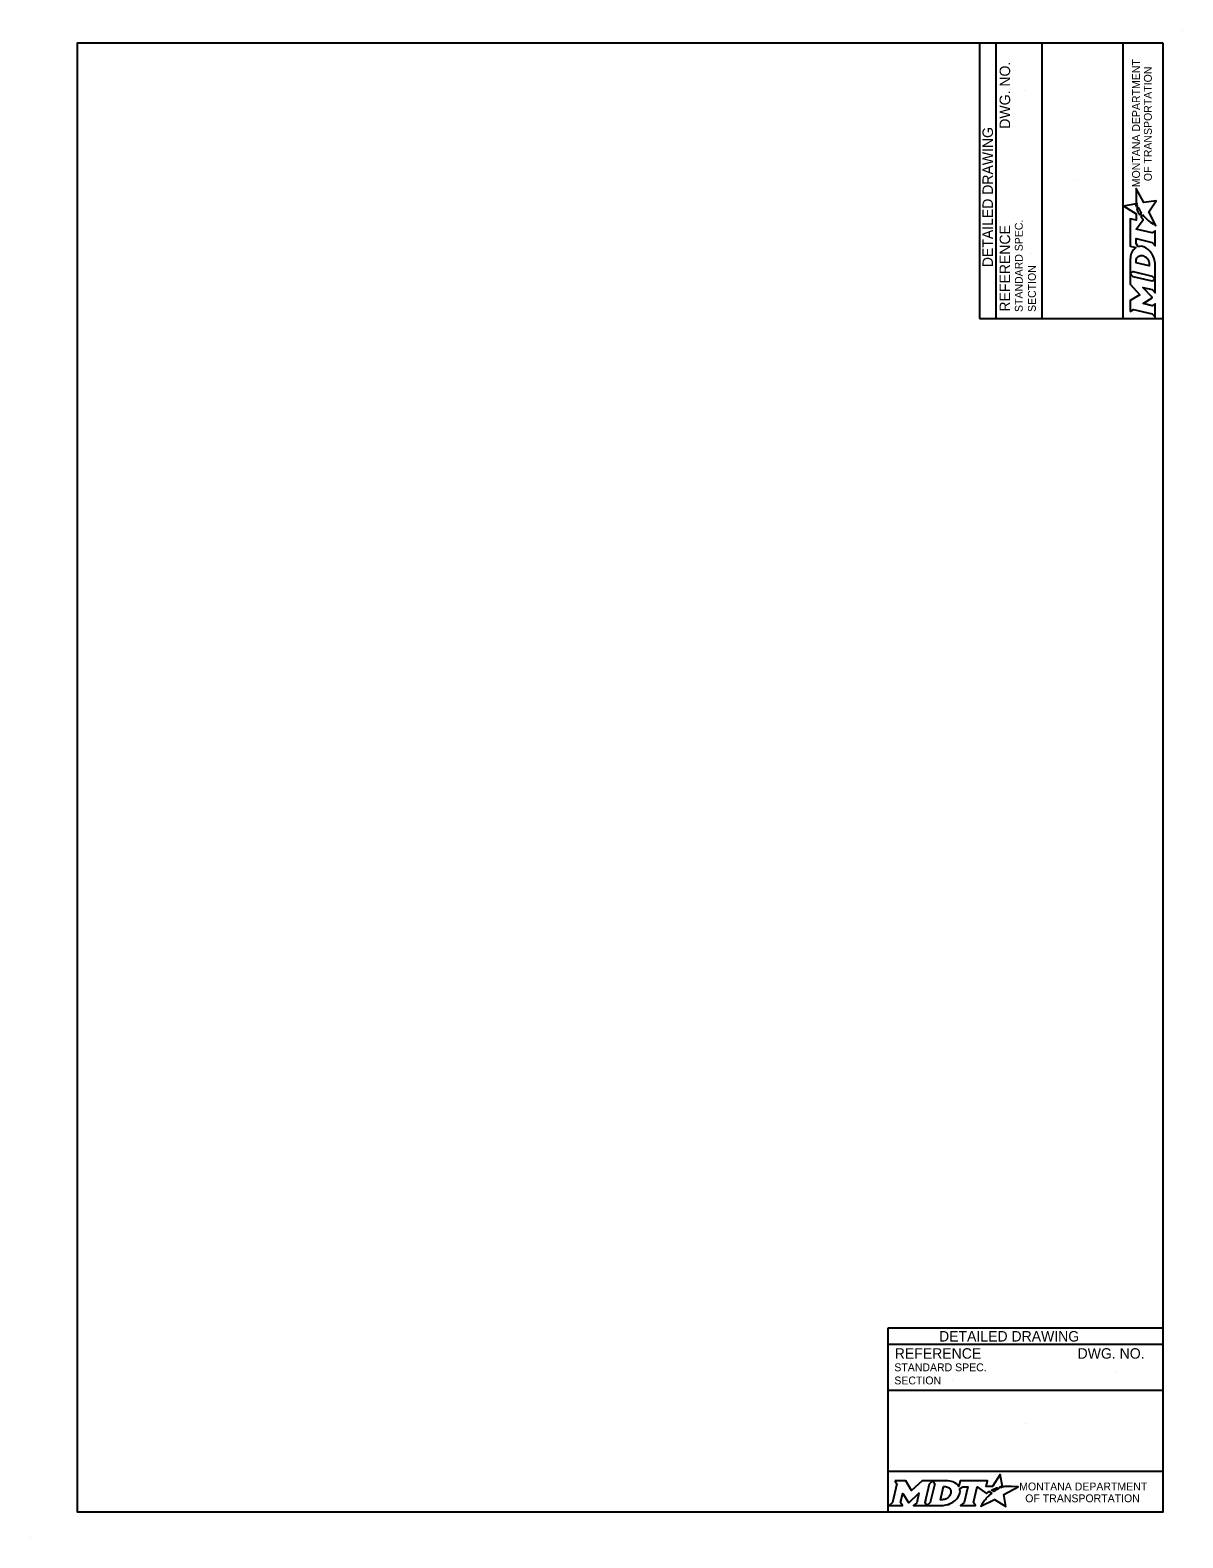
# Model space of a CAD drawing. Extents: x 49991.4 to 50021, y 49987.6 to 50011.4.
# Drawn here: x 49999.98 to 50008.76, y 49999.86 to 50011.36 of the extents above; entities that cross this region are included whole.
import ezdxf

# ---------------------------------------------------------------- set-up
doc = ezdxf.new("R2010")
doc.units = 0
for name, color, linetype in [('Level 1', 7, 'Continuous'), ('Level 2', 7, 'Continuous'), ('Level 3', 7, 'Continuous')]:
    doc.layers.add(name, color=color, linetype=linetype)

msp = doc.modelspace()

# ---------------------------------------------------------------- linework, layer by layer
at = {"layer": 'Level 1'}
for p, q in [((50008.765, 50011.363), (50008.765, 50011.363)), ((49999.977, 49999.862), (49999.977, 49999.862))]:
    msp.add_line(p, q, dxfattribs=at)
msp.add_lwpolyline([(50008.615, 50011.263), (50000.336, 50011.263), (50000.336, 50000.062), (50008.615, 50000.062)], close=True, dxfattribs=at)
at = {"layer": 'Level 2'}
for p, q in [((50008.615, 50001.462), (50006.515, 50001.462)), ((50006.515, 50001.462), (50006.515, 50000.062)), ((50008.615, 50001.337), (50006.515, 50001.337)), ((50008.251, 50001.122), (50008.251, 50001.122)), ((50008.615, 50000.987), (50006.515, 50000.987)), ((50007.009, 50001.063), (50007.009, 50001.063)), ((50007.565, 50000.738), (50007.565, 50000.738)), ((50008.615, 50000.369), (50006.515, 50000.369))]:
    msp.add_line(p, q, dxfattribs=at)
for points in [[(50006.57, 50000.297), (50006.584, 50000.274), (50006.551, 50000.131), (50006.525, 50000.108), (50006.627, 50000.108), (50006.613, 50000.131), (50006.629, 50000.201), (50006.673, 50000.132), (50006.678, 50000.132), (50006.753, 50000.202), (50006.737, 50000.13), (50006.712, 50000.108), (50006.814, 50000.108), (50006.8, 50000.132), (50006.833, 50000.274)], [(50006.833, 50000.274), (50006.859, 50000.297), (50006.776, 50000.297), (50006.697, 50000.224), (50006.652, 50000.297), (50006.57, 50000.297)], [(50006.972, 50000.297), (50006.859, 50000.297), (50006.873, 50000.275), (50006.839, 50000.131), (50006.814, 50000.108), (50006.925, 50000.108)], [(50007.377, 50000.245), (50007.367, 50000.25), (50007.378, 50000.253), (50007.39, 50000.255), (50007.373, 50000.345), (50007.313, 50000.254), (50007.266, 50000.253), (50007.276, 50000.297), (50007.067, 50000.297), (50007.057, 50000.255), (50007.051, 50000.263)], [(50006.996, 50000.211), (50006.995, 50000.203), (50006.992, 50000.193), (50006.988, 50000.185), (50006.982, 50000.178), (50006.976, 50000.171), (50006.968, 50000.164), (50006.959, 50000.16), (50006.95, 50000.156), (50006.941, 50000.154), (50006.932, 50000.153), (50006.916, 50000.153), (50006.94, 50000.253), (50006.956, 50000.253), (50006.963, 50000.252), (50006.971, 50000.25), (50006.977, 50000.247), (50006.983, 50000.243), (50006.988, 50000.238), (50006.992, 50000.232), (50006.995, 50000.226), (50006.996, 50000.218), (50006.996, 50000.215), (50006.996, 50000.211)], [(50007.064, 50000.238), (50007.088, 50000.251), (50007.125, 50000.251), (50007.097, 50000.131), (50007.069, 50000.108), (50007.185, 50000.108), (50007.168, 50000.131), (50007.196, 50000.251), (50007.268, 50000.2), (50007.289, 50000.215), (50007.309, 50000.204)], [(50007.253, 50000.148), (50007.237, 50000.124), (50007.233, 50000.116), (50007.227, 50000.107), (50007.225, 50000.103), (50007.33, 50000.156), (50007.414, 50000.101), (50007.401, 50000.194), (50007.508, 50000.252), (50007.458, 50000.253), (50007.428, 50000.253), (50007.407, 50000.254), (50007.401, 50000.252), (50007.396, 50000.251), (50007.387, 50000.249), (50007.377, 50000.245)], [(50007.327, 50000.217), (50007.324, 50000.215), (50007.306, 50000.225), (50007.316, 50000.231), (50007.32, 50000.233), (50007.329, 50000.237), (50007.335, 50000.239), (50007.343, 50000.243), (50007.35, 50000.245), (50007.362, 50000.238), (50007.358, 50000.236), (50007.353, 50000.233), (50007.349, 50000.231), (50007.344, 50000.228), (50007.342, 50000.227), (50007.339, 50000.225), (50007.337, 50000.224), (50007.334, 50000.222), (50007.332, 50000.221), (50007.329, 50000.219), (50007.327, 50000.217)], [(50006.97, 50000.116), (50006.979, 50000.118), (50006.992, 50000.124), (50007.012, 50000.135)], [(50007.267, 50000.164), (50007.267, 50000.164)]]:
    msp.add_lwpolyline(points, dxfattribs=at)
for centre, radius, start, end in [((50006.951, 50000.236), 0.118, 300.9103, 339.1383), ((50006.995, 50000.219), 0.0709, 339.5329, 15.8582)]:
    msp.add_arc(centre, radius, start, end, dxfattribs=at)
for centre, major_axis, ratio, start_param, end_param in [((50006.97, 50000.25), (0.0834, -0.0037), 0.568097, 0.61298, 1.570796), ((50007.026, 50000.257), (0.0361, -0.0295), 0.469099, 1.225588, 1.570796), ((50007.276, 50000.174), (-0.0098, -0.0102), 0.016458, 3.141593, 6.279097), ((50007.297, 50000.194), (-0.0112, -0.0097), 0.021651, 3.157348, 6.283185), ((50006.925, 50000.257), (0, 0.148), 0.987302, 3.139398, 3.456847), ((50007.26, 50000.156), (-0.00694, -0.00806), 0.008222, 0, 3.137361)]:
    msp.add_ellipse(centre, major_axis=major_axis, ratio=ratio, start_param=start_param, end_param=end_param, dxfattribs=at)
at = {"layer": 'Level 3'}
for p, q in [((50007.215, 50011.263), (50007.215, 50009.163)), ((50007.34, 50011.263), (50007.34, 50009.163)), ((50007.69, 50011.263), (50007.69, 50009.163)), ((50008.308, 50011.263), (50008.308, 50009.163)), ((50007.555, 50010.899), (50007.555, 50010.899)), ((50007.939, 50010.213), (50007.939, 50010.213)), ((50007.614, 50009.657), (50007.614, 50009.657)), ((50007.215, 50009.163), (50008.615, 50009.163))]:
    msp.add_line(p, q, dxfattribs=at)
for points in [[(50008.514, 50009.9), (50008.538, 50009.885), (50008.546, 50009.88), (50008.554, 50009.875), (50008.559, 50009.872), (50008.505, 50009.978), (50008.561, 50010.061), (50008.468, 50010.048), (50008.409, 50010.155), (50008.409, 50010.106), (50008.408, 50010.076), (50008.408, 50010.055), (50008.409, 50010.048), (50008.411, 50010.043), (50008.413, 50010.035), (50008.417, 50010.025)], [(50008.417, 50010.025), (50008.411, 50010.014), (50008.409, 50010.026), (50008.407, 50010.038), (50008.316, 50010.02), (50008.408, 50009.961), (50008.408, 50009.914), (50008.364, 50009.924), (50008.364, 50009.715), (50008.407, 50009.705), (50008.398, 50009.699)], [(50008.423, 50009.711), (50008.41, 50009.736), (50008.41, 50009.773), (50008.531, 50009.744), (50008.553, 50009.717), (50008.553, 50009.833), (50008.531, 50009.816), (50008.41, 50009.844), (50008.462, 50009.915), (50008.447, 50009.937), (50008.458, 50009.956)], [(50008.445, 50009.974), (50008.446, 50009.972), (50008.437, 50009.954), (50008.431, 50009.964), (50008.429, 50009.968), (50008.425, 50009.977), (50008.422, 50009.982), (50008.419, 50009.99), (50008.416, 50009.998), (50008.424, 50010.009), (50008.426, 50010.005), (50008.428, 50010.001), (50008.431, 50009.997), (50008.434, 50009.992), (50008.435, 50009.99), (50008.436, 50009.987), (50008.438, 50009.985), (50008.439, 50009.982), (50008.441, 50009.98), (50008.443, 50009.977), (50008.445, 50009.974)], [(50008.498, 50009.914), (50008.498, 50009.914)], [(50008.364, 50009.62), (50008.364, 50009.506), (50008.387, 50009.521), (50008.531, 50009.487), (50008.553, 50009.462), (50008.553, 50009.572)], [(50008.451, 50009.644), (50008.459, 50009.643), (50008.468, 50009.64), (50008.476, 50009.635), (50008.484, 50009.63), (50008.491, 50009.623), (50008.497, 50009.615), (50008.502, 50009.607), (50008.506, 50009.598), (50008.508, 50009.589), (50008.509, 50009.58), (50008.509, 50009.564), (50008.409, 50009.587), (50008.409, 50009.603), (50008.41, 50009.611), (50008.412, 50009.619), (50008.415, 50009.625), (50008.419, 50009.631), (50008.424, 50009.636), (50008.43, 50009.64), (50008.436, 50009.642), (50008.443, 50009.644), (50008.446, 50009.644), (50008.451, 50009.644)], [(50008.546, 50009.618), (50008.543, 50009.626), (50008.538, 50009.639), (50008.527, 50009.66)], [(50008.387, 50009.481), (50008.364, 50009.506), (50008.364, 50009.424), (50008.437, 50009.344), (50008.364, 50009.3), (50008.364, 50009.218)], [(50008.364, 50009.218), (50008.388, 50009.232), (50008.531, 50009.198), (50008.553, 50009.173), (50008.553, 50009.274), (50008.531, 50009.261), (50008.461, 50009.277), (50008.53, 50009.321), (50008.53, 50009.326), (50008.46, 50009.401), (50008.531, 50009.385), (50008.553, 50009.36), (50008.553, 50009.462), (50008.53, 50009.448), (50008.387, 50009.481)]]:
    msp.add_lwpolyline(points, dxfattribs=at)
for centre, radius, start, end in [((50008.443, 50009.643), 0.0709, 69.5329, 105.8582), ((50008.425, 50009.599), 0.118, 30.9103, 69.1383)]:
    msp.add_arc(centre, radius, start, end, dxfattribs=at)
for centre, major_axis, ratio, start_param, end_param in [((50008.468, 50009.945), (0.0097, -0.0112), 0.021651, 3.157348, 6.283185), ((50008.487, 50009.924), (0.0102, -0.0098), 0.016458, 3.141593, 6.279097), ((50008.506, 50009.907), (0.00806, -0.00694), 0.008222, 0, 3.137361), ((50008.412, 50009.618), (0.0037, 0.0834), 0.568097, 0.61298, 1.570796), ((50008.404, 50009.673), (0.0295, 0.0361), 0.469099, 1.225588, 1.570796), ((50008.405, 50009.573), (-0.148, 0), 0.987302, 3.139398, 3.456847)]:
    msp.add_ellipse(centre, major_axis=major_axis, ratio=ratio, start_param=start_param, end_param=end_param, dxfattribs=at)

# ---------------------------------------------------------------- texts
at = {"layer": 'Level 2'}
for s, height, p in [('DETAILED DRAWING', 0.0799, (50006.906, 50001.36)), ('REFERENCE', 0.08, (50006.568, 50001.229)), ('DWG. NO.', 0.08, (50007.962, 50001.229)), ('STANDARD SPEC.', 0.06, (50006.565, 50001.133)), ('SECTION', 0.06, (50006.565, 50001.033))]:
    msp.add_text(s, height=height, dxfattribs=at).set_placement(p)
for s, p in [('MONTANA DEPARTMENT', (50007.517, 50000.224)), ('OF TRANSPORTATION', (50007.563, 50000.134))]:
    msp.add_text(s, height=0.06, rotation=360, dxfattribs=at).set_placement(p)
at = {"layer": 'Level 3'}
for s, height, p in [('DWG. NO.', 0.08, (50007.448, 50010.611)), ('MONTANA DEPARTMENT', 0.06, (50008.438, 50010.165)), ('OF TRANSPORTATION', 0.06, (50008.528, 50010.211)), ('DETAILED DRAWING', 0.0799, (50007.317, 50009.555)), ('REFERENCE', 0.08, (50007.448, 50009.216)), ('STANDARD SPEC.', 0.06, (50007.544, 50009.213)), ('SECTION', 0.06, (50007.644, 50009.213))]:
    msp.add_text(s, height=height, rotation=90, dxfattribs=at).set_placement(p)

doc.saveas('drawing.dxf')
